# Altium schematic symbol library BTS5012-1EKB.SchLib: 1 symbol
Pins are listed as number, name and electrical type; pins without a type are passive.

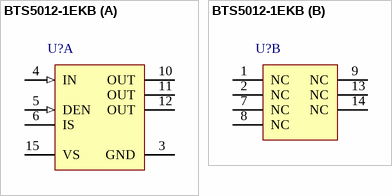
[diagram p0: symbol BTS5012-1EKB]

## BTS5012-1EKB
designator U?
PROFET+ 12 V Smart High-Side Power Switch, 1 Channel, 12 mohm, 10 A Load Current, -40 to 150 degC, PG-DSO-14-47, Reel, Green; Manufacturer: Infineon; PartNumber: BTS5012-1EKB; Channels: 1; Green: TRUE; Group: Automotive Qualified; Load Current (typ): 10 A; Ptot (max): 2 mW; Recommended Operating Voltage Max.: 28 V; Recommended Operating Voltage Min.: 5 V; RON @ 25degreesC: 12 mOhm; RON(max) @ 150degreesC: 24 mOhm; toff (max): 250 us
footprint INF-PG-DSO-14-47_N (SOP, 14-Leads, Body 8.65x3.9mm, Pitch 1.27mm, Thermal Pad 6500x2750mm, IPC Medium Density)
footprint INF-PG-DSO-14-47_L (SOP, 14-Leads, Body 8.65x3.9mm, Pitch 1.27mm, Thermal Pad 6500x2750mm, IPC High Density)
footprint INF-PG-DSO-14-47_M (SOP, 14-Leads, Body 8.65x3.9mm, Pitch 1.27mm, Thermal Pad 6500x2750mm, IPC Low Density)
part A pins: 3 GND (power) "GrouND; Ground connection", 4 IN (in) "INput channel; Input signal for channel activation", 5 DEN (in) "Diagnostic ENable; Digital signal to enable/disable the diagnosis of the device", 6 IS (hiz) "Sense; Sense current of the selected channel", 10 OUT (power) "OUTput; Protected high side power output channel", 11 OUT (power) "OUTput; Protected high side power output channel", 12 OUT (power) "OUTput; Protected high side power output channel", 15 VS (power) "Voltage Supply; Battery voltage"
part B pins: 1 NC "Not Connected; No internal connection to the chip", 2 NC "Not Connected; No internal connection to the chip", 7 NC "Not Connected; No internal connection to the chip", 8 NC "Not Connected; No internal connection to the chip", 9 NC "Not Connected; No internal connection to the chip", 13 NC "Not Connected; No internal connection to the chip", 14 NC "Not Connected; No internal connection to the chip"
